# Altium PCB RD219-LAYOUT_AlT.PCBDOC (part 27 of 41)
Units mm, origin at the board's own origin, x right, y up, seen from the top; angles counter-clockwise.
Board outline 209.75 x 159.97 mm, 2 copper layers (TOP, BOTTOM), stack 0 mm thick; 398 components, 199 nets, 1469 pads, 0 vias.
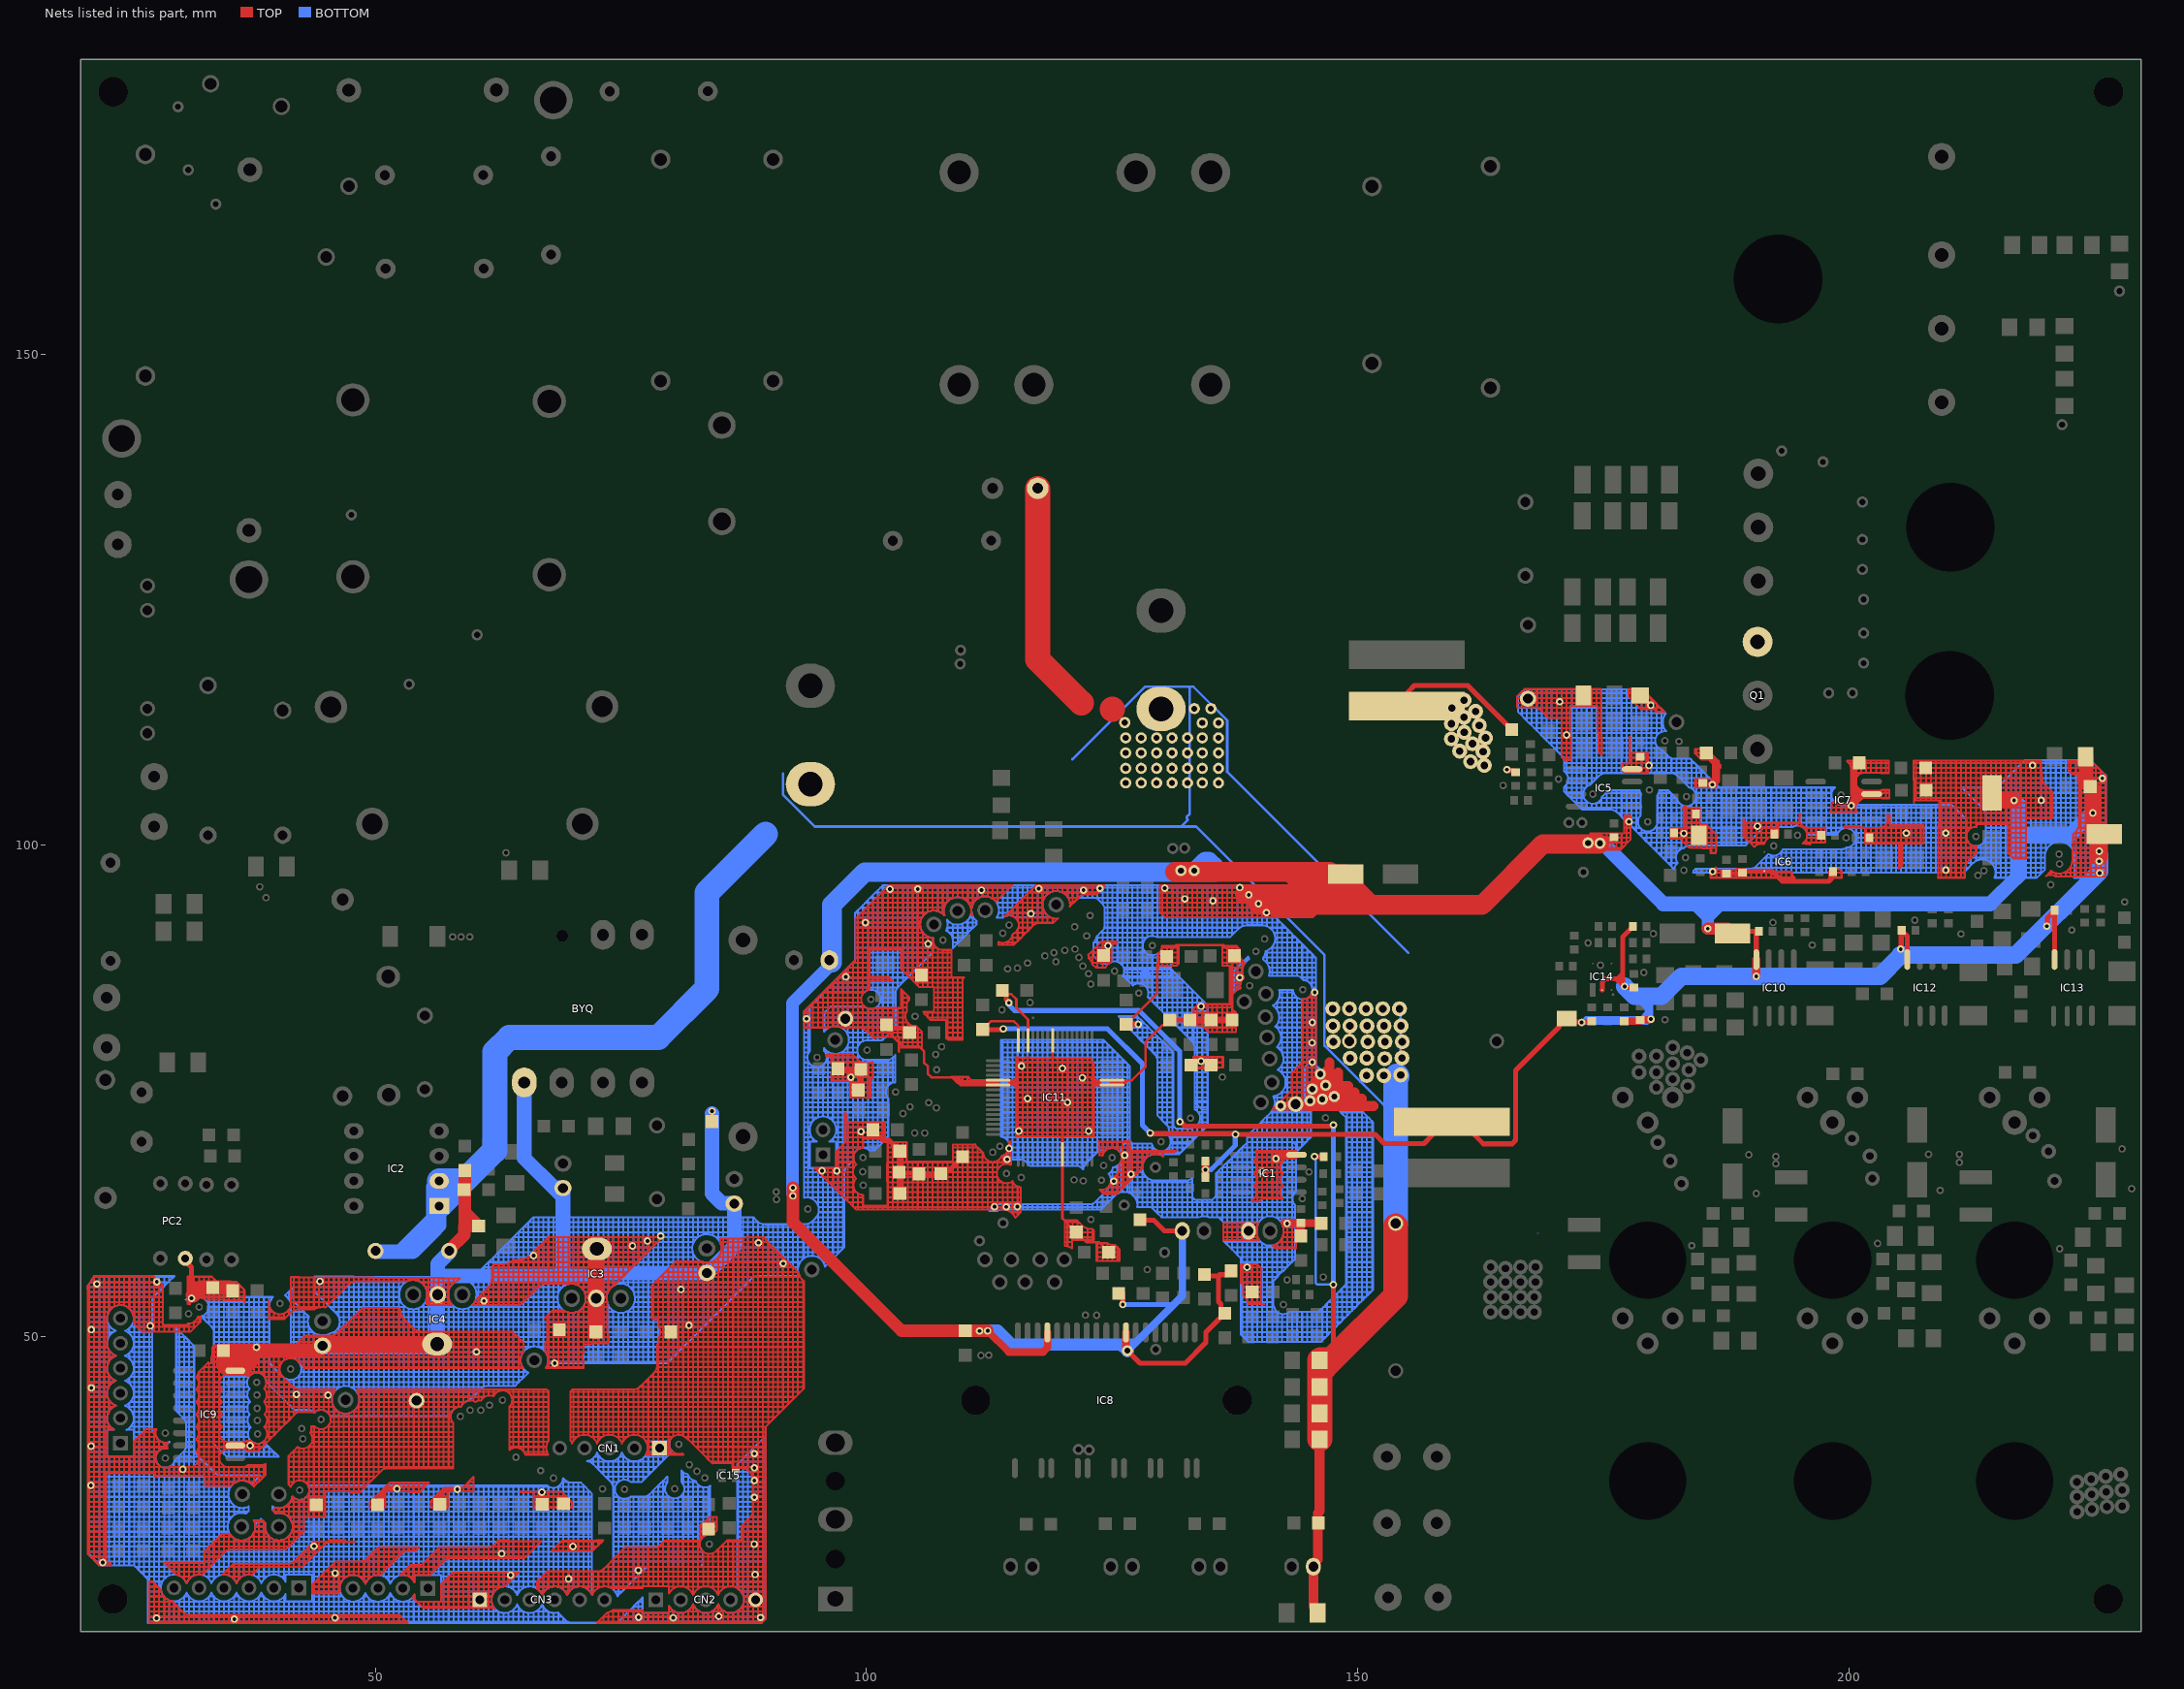
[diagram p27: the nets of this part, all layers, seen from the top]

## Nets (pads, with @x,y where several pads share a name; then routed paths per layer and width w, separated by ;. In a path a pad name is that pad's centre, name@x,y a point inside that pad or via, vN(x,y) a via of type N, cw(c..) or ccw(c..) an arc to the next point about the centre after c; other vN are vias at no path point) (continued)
GND: (continued)
  BOTTOM w0.203: 72.705,61.656 73.213,61.656 ; 72.705,62.164 73.213,62.164 ; 72.83,37.78 ccw(c73.848,38.669) 73.213,37.476 73.213,37.272 ; 72.949,36.256 73.213,36.256 ; 72.949,36.256 73.213,35.992 ; 73.213,35.992 73.213,36.256 ; 73.213,35.992 73.457,35.748 ; 73.213,36.256 73.213,36.764 ; 73.213,36.256 73.721,36.256 ; 73.213,36.764 73.213,37.272 ; 73.213,36.764 73.721,36.764 ; 73.213,37.272 73.721,37.272 ; 73.213,47.319 73.213,47.432 ; 73.213,47.319 73.721,47.319 ; 73.213,47.432 73.213,47.94 ; 73.213,47.432 73.721,47.432 ; 73.213,47.94 73.213,48.448 ; 73.213,47.94 73.721,47.94 ; 73.213,48.448 73.213,48.956 ; 73.213,48.448 73.721,48.448 ; 73.213,48.956 73.213,49.464 ; 73.213,48.956 73.721,48.956 ; 73.213,49.464 73.213,49.972 ; 73.213,49.464 73.721,49.464 ; 73.213,49.972 73.213,50.48 ; 73.213,49.972 73.721,49.972 ; 73.213,50.48 73.213,50.988 ; 73.213,50.48 73.721,50.48 ; 73.213,50.988 73.213,51.496 ; 73.213,50.988 73.721,50.988 ; 73.213,51.496 73.213,52.004 ; 73.213,51.496 73.721,51.496 ; 73.213,52.004 73.213,52.512 ; 73.213,52.004 73.721,52.004 ; 73.213,52.512 73.213,53.02 ; 73.213,52.512 73.721,52.512 ; 73.213,53.02 IC3.2@73.213,53.528 ; 73.213,53.02 73.721,53.02 ; IC3.2@73.213,53.528 73.6,53.528 ; IC3.2@73.213,53.528 IC3.2@73.213,54.036 ; IC3.2@73.213,54.036 73.213,54.544 ; IC3.2@73.213,54.036 73.565,54.036 ; 73.213,54.544 73.213,55.052 ; 73.213,54.544 73.683,54.544 ; 73.213,55.052 73.213,55.56 ; 73.213,55.052 73.721,55.052 ; 73.213,55.56 73.213,56.068 ; 73.213,55.56 73.721,55.56 ; 73.213,56.068 73.213,56.489 73.213,56.576 ; 73.213,56.068 73.721,56.068 ; 73.213,56.576 73.213,57.084 ; 73.213,56.576 73.721,56.576 ; 73.213,57.084 73.213,57.592 ; 73.213,57.084 73.721,57.084 ; 73.213,57.592 IC3.4@73.213,58.1 ; 73.213,57.592 73.721,57.592 ; IC3.4@73.213,58.1 IC3.4@73.213,58.608 ; IC3.4@73.213,58.1 73.721,58.1 ; IC3.4@73.213,58.608 IC3.4@73.721,58.608 ; IC3.4@73.213,58.608 IC3.4@73.213,59.116 ; IC3.4@73.213,59.116 IC3.4@73.213,59.624 ; IC3.4@73.213,59.116 IC3.4@73.721,59.116 ; IC3.4@73.213,59.624 73.213,60.132 ; IC3.4@73.213,59.624 IC3.4@73.721,59.624 ; 73.213,60.132 73.213,60.64 ; 73.213,60.132 73.721,60.132 ; 73.213,60.64 73.213,61.148 ; 73.213,60.64 73.721,60.64 ; 73.213,61.148 73.213,61.656 ; 73.213,61.148 73.721,61.148 ; 73.213,61.656 73.213,62.164 ; 73.213,61.656 73.721,61.656 ; 73.213,62.164 73.721,62.164 ; 73.457,35.748 73.721,35.748 ; 73.457,35.748 73.721,35.484 ; 73.565,54.036 ccw(c74.991,53.973) 73.564,53.973 73.564,53.846 ccw(c74.991,53.846) 73.6,53.528 ; 73.565,54.036 cw(c74.991,53.973) 73.683,54.544 ; 73.6,53.528 ccw(c74.991,53.846) 73.6,53.524 ccw(c74.991,53.846) 73.719,53.198 ccw(c74.991,53.846) 73.721,53.195 ; 73.683,54.544 cw(c74.991,53.973) 73.719,54.62 cw(c74.991,53.973) 73.721,54.623 ; 73.721,35.484 73.721,35.748 ; 73.721,35.748 73.721,36.256 ; 73.721,35.748 74.229,35.748 ; 73.721,36.256 73.721,36.764 ; 73.721,36.256 74.229,36.256 ; 73.721,36.764 73.721,37.272 ; 73.721,36.764 74.229,36.764 ; 73.721,37.272 74.229,37.272 ; 73.721,37.272 73.721,37.323 ; 73.721,37.323 ccw(c73.848,38.669) 73.848,37.317 ccw(c73.848,38.669) 74.229,37.372 ; 73.721,47.319 73.721,47.432 ; 73.721,47.319 74.229,47.319 ; 73.721,47.432 73.721,47.94 ; 73.721,47.432 74.229,47.432 ; 73.721,47.94 73.721,48.448 ; 73.721,47.94 74.229,47.94 ; 73.721,48.448 73.721,48.956 ; 73.721,48.448 74.229,48.448 ; 73.721,48.956 73.721,49.464 ; 73.721,48.956 74.229,48.956 ; 73.721,49.464 73.721,49.972 ; 73.721,49.464 74.229,49.464 ; 73.721,49.972 73.721,50.48 ; 73.721,49.972 74.229,49.972 ; 73.721,50.48 73.721,50.988 ; 73.721,50.48 74.229,50.48 ; 73.721,50.988 73.721,51.496 ; 73.721,50.988 74.229,50.988 ; 73.721,51.496 73.721,52.004 ; 73.721,51.496 74.229,51.496 ; 73.721,52.004 73.721,52.512 ; 73.721,52.004 74.229,52.004 ; 73.721,52.512 73.721,53.02 ; 73.721,52.512 74.229,52.512 ; 73.721,53.02 73.721,53.195 ; 73.721,53.02 73.827,53.02 ; 73.721,53.195 ccw(c74.991,53.846) 73.822,53.027 ccw(c74.991,53.846) 73.827,53.02 ; 73.721,54.623 cw(c74.991,53.973) 74.055,55.05 cw(c74.991,53.973) 74.058,55.052 ; 73.721,54.623 73.721,55.052 ; 73.721,55.052 73.721,55.56 ; 73.721,55.052 74.058,55.052 ; 73.721,55.56 73.721,56.068 ; 73.721,55.56 74.229,55.56 ; 73.721,56.068 73.721,56.489 73.721,56.576 ; 73.721,56.068 74.229,56.068 ; 73.721,56.576 73.721,57.084 ; 73.721,56.576 74.229,56.576 ; 73.721,57.084 73.721,57.592 ; 73.721,57.084 74.229,57.084 ; 73.721,57.592 73.721,58.1 ; 73.721,57.592 74.229,57.592 ; 73.721,58.1 IC3.4@73.721,58.608 ; 73.721,58.1 74.229,58.1 ; IC3.4@73.721,58.608 74.229,58.608 ; IC3.4@73.721,58.608 IC3.4@73.721,59.116 ; IC3.4@73.721,59.116 IC3.4@73.721,59.624 ; IC3.4@73.721,59.116 74.229,59.116 ; IC3.4@73.721,59.624 73.721,60.132 ; IC3.4@73.721,59.624 74.229,59.624 ; 73.721,60.132 73.721,60.64 ; 73.721,60.132 74.229,60.132 ; 73.721,60.64 73.721,61.148 ; 73.721,60.64 74.229,60.64 ; 73.721,61.148 73.721,61.656 ; 73.721,61.148 74.229,61.148 ; 73.721,61.656 73.721,62.164 ; 73.721,61.656 74.229,61.656 ; 73.721,62.164 74.229,62.164 ; 73.962,35.24 ccw(c73.135,34.512) 73.914,35.291 cw(c73.135,34.512) 73.962,35.24 ; 73.962,35.24 cw(c73.135,34.512) 74.215,34.732 ; 73.962,35.24 cw(c73.135,34.512) 74.215,34.732 ; 73.962,35.24 74.229,35.24 ; 74.058,55.052 cw(c74.991,53.973) 74.229,55.179 ; 74.215,34.732 cw(c73.135,34.512) 74.229,34.642 ; 74.215,34.732 cw(c73.135,34.512) 74.229,34.642 ; 74.215,34.732 74.229,34.732 ; 74.229,34.642 cw(c73.135,34.512) 74.237,34.512 ; 74.229,34.642 cw(c73.135,34.512) 74.237,34.512 ; 74.229,34.642 74.229,34.732 ; 74.229,34.732 74.229,35.24 ; 74.229,34.732 74.423,34.732 ; 74.229,35.24 74.737,35.24 ; 74.229,35.24 74.229,35.748 ; 74.229,35.748 74.229,36.256 ; 74.229,35.748 74.737,35.748 ; 74.229,36.256 74.229,36.764 ; 74.229,36.256 74.737,36.256 ; 74.229,36.764 74.229,37.272 ; 74.229,36.764 74.737,36.764 ; 74.229,37.272 74.737,37.272 ; 74.229,37.272 74.229,37.372 ; 74.229,37.372 ccw(c73.848,38.669) 74.737,37.651 ; 74.229,47.319 74.229,47.432 ; 74.229,47.319 74.737,47.319 ; 74.229,47.432 74.229,47.94 ; 74.229,47.432 74.737,47.432 ; 74.229,47.94 74.229,48.448 ; 74.229,47.94 74.737,47.94 ; 74.229,48.448 74.229,48.956 ; 74.229,48.448 74.737,48.448 ; 74.229,48.956 74.229,49.464 ; 74.229,48.956 74.737,48.956 ; 74.229,49.464 74.229,49.972 ; 74.229,49.464 74.737,49.464 ; 74.229,49.972 74.229,50.48 ; 74.229,49.972 74.737,49.972 ; 74.229,50.48 74.229,50.988 ; 74.229,50.48 74.737,50.48 ; 74.229,50.988 74.229,51.496 ; 74.229,50.988 74.737,50.988 ; 74.229,51.496 74.229,52.004 ; 74.229,51.496 74.737,51.496 ; 74.229,52.004 74.229,52.512 ; 74.229,52.004 74.737,52.004 ; 74.229,52.512 74.483,52.512 ; 74.229,55.179 cw(c74.991,53.973) 74.235,55.183 cw(c74.991,53.973) 74.737,55.377 ; 74.229,55.179 74.229,55.56 ; 74.229,55.56 74.229,56.068 ; 74.229,55.56 74.737,55.56 ; 74.229,56.068 74.229,56.489 74.229,56.576 ; 74.229,56.068 74.737,56.068 ; 74.229,56.576 74.229,57.084 ; 74.229,56.576 74.737,56.576 ; 74.229,57.084 74.229,57.592 ; 74.229,57.084 74.737,57.084 ; 74.229,57.592 74.229,58.1 ; 74.229,57.592 74.737,57.592 ; 74.229,58.1 74.229,58.608 ; 74.229,58.1 74.737,58.1 ; 74.229,58.608 74.229,59.116 ; 74.229,58.608 74.737,58.608 ; 74.229,59.116 74.229,59.624 ; 74.229,59.116 74.737,59.116 ; 74.229,59.624 74.229,60.132 ; 74.229,59.624 74.737,59.624 ; 74.229,60.132 74.229,60.64 ; 74.229,60.132 74.737,60.132 ; 74.229,60.64 74.229,61.148 ; 74.229,60.64 74.737,60.64 ; 74.229,61.148 74.229,61.656 ; 74.229,61.148 74.737,61.148 ; 74.229,61.656 74.229,62.164 ; 74.229,61.656 74.737,61.656 ; 74.229,62.164 74.737,62.164 ; 74.237,24.252 cw(c73.34,23.241) 74.405,24.073 cw(c73.34,23.241) 74.412,24.064 ; 74.237,24.252 74.237,24.572 ; 74.237,24.572 74.237,25.08 ; 74.237,24.572 74.737,24.572 ; 74.237,25.08 74.737,25.08 ; 74.237,25.08 74.237,25.588 ; 74.237,25.588 74.237,26.096 ; 74.237,25.588 74.737,25.588 ; 74.237,26.096 74.737,26.096 ; 74.237,26.096 74.237,26.604 ; 74.237,26.604 74.737,26.604 ; 74.237,26.604 74.237,27.112 ; 74.237,27.112 74.737,27.112 ; 74.237,27.112 74.237,27.62 ; 74.237,27.62 74.237,28.128 ; 74.237,27.62 74.737,27.62 ; 74.237,28.128 74.737,28.128 ; 74.237,28.128 74.237,28.636 ; 74.237,28.636 74.737,28.636 ; 74.237,28.636 74.237,29.144 ; 74.237,29.144 74.237,29.652 ; 74.237,29.144 74.737,29.144 ; 74.237,29.652 74.737,29.652 ; 74.237,29.652 74.237,30.16 ; 74.237,30.16 74.737,30.16 ; 74.237,30.16 74.237,30.668 ; 74.237,30.668 74.737,30.668 ; 74.237,30.668 74.237,31.176 ; 74.237,31.176 74.737,31.176 ; 74.237,31.176 74.237,31.684 ; 74.237,31.684 74.737,31.684 ; 74.237,31.684 74.237,32.192 ; 74.237,32.192 74.737,32.192 ; 74.237,32.192 74.237,32.7 ; 74.237,32.7 74.737,32.7 ; 74.237,32.7 74.237,33.208 ; 74.237,33.208 74.237,33.716 ; 74.237,33.208 74.737,33.208 ; 74.237,33.716 74.237,34.224 ; 74.237,33.716 74.737,33.716 ; 74.237,34.224 74.423,34.224 ; 74.237,34.224 74.237,34.512 ; 74.356,20.922 ccw(c74.356,21.651) 74.713,21.016 ; 74.356,20.922 ccw(c74.356,21.651) 74.713,21.016 ; 74.412,24.064 74.737,24.064 ; 74.423,34.224 ccw(c75.372,34.478) 74.737,33.728 ; 74.423,34.224 cw(c75.372,34.478) 74.423,34.732 ; 74.423,34.732 cw(c75.372,34.478) 74.737,35.228 ; 74.483,52.512 ccw(c74.991,53.846) 74.737,52.441 ; 74.713,21.016 ccw(c74.356,21.651) 74.737,21.03 ; 74.713,21.016 ccw(c74.356,21.651) 74.737,21.03 ; 74.713,21.016 74.737,21.016 ; 74.737,20.889 75.245,20.889 ; 74.737,20.889 74.737,21.016 ; 74.737,21.016 75.245,21.016 ; 74.737,21.016 74.737,21.03 ; 74.737,21.03 ccw(c74.356,21.651) 74.871,21.136 ; 74.737,21.03 ccw(c74.356,21.651) 74.871,21.136 ; 74.737,23.697 74.737,24.064 ; 74.737,23.697 75.104,24.064 ; 74.737,24.064 74.737,24.572 ; 74.737,24.064 75.104,24.064 ; 74.737,24.572 74.737,25.08 ; 74.737,24.572 75.245,24.572 ; 74.737,25.08 75.245,25.08 ; 74.737,25.08 74.737,25.588 ; 74.737,25.588 74.737,26.096 ; 74.737,25.588 75.245,25.588 ; 74.737,26.096 75.245,26.096 ; 74.737,26.096 74.737,26.604 ; 74.737,26.604 75.245,26.604 ; 74.737,26.604 74.737,27.112 ; 74.737,27.112 74.737,27.62 ; 74.737,27.112 75.245,27.112 ; 74.737,27.62 74.737,28.128 ; 74.737,27.62 75.245,27.62 ; 74.737,28.128 74.737,28.636 ; 74.737,28.128 75.245,28.128 ; 74.737,28.636 74.737,29.144 ; 74.737,28.636 75.245,28.636 ; 74.737,29.144 74.737,29.652 ; 74.737,29.144 75.245,29.144 ; 74.737,29.652 75.245,29.652 ; 74.737,29.652 74.737,30.16 ; 74.737,30.16 74.737,30.668 ; 74.737,30.16 75.245,30.16 ; 74.737,30.668 74.737,31.176 ; 74.737,30.668 75.245,30.668 ; 74.737,31.176 74.737,31.684 ; 74.737,31.176 75.245,31.176 ; 74.737,31.684 74.737,32.192 ; 74.737,31.684 75.245,31.684 ; 74.737,32.192 74.737,32.7 ; 74.737,32.192 75.245,32.192 ; 74.737,32.7 74.737,33.208 ; 74.737,32.7 75.245,32.7 ; 74.737,33.208 74.737,33.716 ; 74.737,33.208 75.245,33.208 ; 74.737,33.716 74.737,33.728 ; 74.737,33.716 74.752,33.716 ; 74.737,33.728 ccw(c75.372,34.478) 74.752,33.716 ; 74.737,35.228 cw(c75.372,34.478) 74.752,35.24 ; 74.737,35.228 74.737,35.24 ; 74.737,35.24 74.737,35.748 ; 74.737,35.24 74.752,35.24 ; 74.737,35.748 74.737,36.256 ; 74.737,35.748 75.245,35.748 ; 74.737,36.256 74.737,36.764 ; 74.737,36.256 75.245,36.256 ; 74.737,36.764 74.737,37.272 ; 74.737,36.764 75.245,36.764 ; 74.737,37.272 75.245,37.272 ; 74.737,37.272 74.737,37.651 ; 74.737,37.651 ccw(c73.848,38.669) 74.866,37.78 ; 74.737,47.319 74.737,47.432 ; 74.737,47.319 75.245,47.319 ; 74.737,47.432 74.737,47.94 ; 74.737,47.432 75.245,47.432 ; 74.737,47.94 74.737,48.448 ; 74.737,47.94 75.245,47.94 ; 74.737,48.448 74.737,48.956 ; 74.737,48.448 75.245,48.448 ; 74.737,48.956 74.737,49.464 ; 74.737,48.956 75.245,48.956 ; 74.737,49.464 74.737,49.972 ; 74.737,49.464 75.245,49.464 ; 74.737,49.972 74.737,50.48 ; 74.737,49.972 75.245,49.972 ; 74.737,50.48 74.737,50.988 ; 74.737,50.48 75.245,50.48 ; 74.737,50.988 74.737,51.496 ; 74.737,50.988 75.245,50.988 ; 74.737,51.496 74.737,52.004 ; 74.737,51.496 75.245,51.496 ; 74.737,52.004 75.245,52.004 ; 74.737,52.004 74.737,52.441 ; 74.737,52.441 ccw(c74.991,53.846) 74.743,52.44 ccw(c74.991,53.846) 75.245,52.441 ; 74.737,55.377 cw(c74.991,53.973) 74.743,55.378 cw(c74.991,53.973) 74.991,55.4 cw(c74.991,53.973) 75.239,55.378 cw(c74.991,53.973) 75.245,55.377 ; 74.737,55.377 74.737,55.56 ; 74.737,55.56 74.737,56.068 ; 74.737,55.56 75.245,55.56 ; 74.737,56.068 74.737,56.489 74.737,56.576 ; 74.737,56.068 75.245,56.068 ; 74.737,56.576 74.737,57.084 ; 74.737,56.576 75.245,56.576 ; 74.737,57.084 74.737,57.592 ; 74.737,57.084 75.245,57.084 ; 74.737,57.592 74.737,58.1 ; 74.737,57.592 75.245,57.592 ; 74.737,58.1 74.737,58.608 ; 74.737,58.1 75.245,58.1 ; 74.737,58.608 74.737,59.116 ; 74.737,58.608 75.245,58.608 ; 74.737,59.116 74.737,59.624 ; 74.737,59.116 75.245,59.116 ; 74.737,59.624 74.737,60.132 ; 74.737,59.624 75.245,59.624 ; 74.737,60.132 74.737,60.64 ; 74.737,60.132 75.245,60.132 ; 74.737,60.64 74.737,61.148 ; 74.737,60.64 75.245,60.64 ; 74.737,61.148 74.737,61.656 ; 74.737,61.148 75.245,61.148 ; 74.737,61.656 74.737,62.164 ; 74.737,61.656 75.245,61.656 ; 74.737,62.164 75.245,62.164 ; 74.752,33.716 ccw(c75.372,34.478) 75.245,33.504 ; 74.752,35.24 cw(c75.372,34.478) 75.245,35.452 ; 74.866,37.78 ccw(c73.848,38.669) 75.118,38.206 ccw(c76.388,38.669) 75.242,37.953 ccw(c76.388,38.669) 75.245,37.948 ; 74.866,37.78 75.245,37.78 ; 74.871,21.136 75.259,21.524 ; 75.104,24.064 75.245,24.205 ; 75.245,20.889 75.753,20.889 ; 75.245,20.889 75.245,21.016 ; 75.245,21.016 75.753,21.016 ; 75.245,24.205 75.245,24.572 ; 75.245,24.205 75.612,24.572 ; 75.245,24.572 75.245,25.08 ; 75.245,24.572 75.612,24.572 ; 75.245,25.08 75.245,25.588 ; 75.245,25.08 75.753,25.08 ; 75.245,25.588 75.245,26.096 ; 75.245,25.588 75.753,25.588 ; 75.245,26.096 75.245,26.604 ; 75.245,26.096 75.753,26.096 ; 75.245,26.604 75.245,27.112 ; 75.245,26.604 75.753,26.604 ; 75.245,27.112 75.245,27.62 ; 75.245,27.112 75.753,27.112 ; 75.245,27.62 75.245,28.128 ; 75.245,27.62 75.753,27.62 ; 75.245,28.128 75.245,28.636 ; 75.245,28.128 75.753,28.128 ; 75.245,28.636 75.245,29.144 ; 75.245,28.636 75.753,28.636 ; 75.245,29.144 75.245,29.652 ; 75.245,29.144 75.753,29.144 ; 75.245,29.652 75.245,30.16 ; 75.245,29.652 75.753,29.652 ; 75.245,30.16 75.245,30.668 ; 75.245,30.16 75.753,30.16 ; 75.245,30.668 75.245,31.176 ; 75.245,30.668 75.753,30.668 ; 75.245,31.176 75.245,31.684 ; 75.245,31.176 75.753,31.176 ; 75.245,31.684 75.245,32.192 ; 75.245,31.684 75.753,31.684 ; 75.245,32.192 75.245,32.7 ; 75.245,32.192 75.753,32.192 ; 75.245,32.7 75.245,33.208 ; 75.245,32.7 75.753,32.7 ; 75.245,33.208 75.753,33.208 ; 75.245,33.208 75.245,33.504 ; 75.245,33.504 ccw(c75.372,34.478) 75.252,33.503 ccw(c75.372,34.478) 75.753,33.572 ; 75.245,35.452 cw(c75.372,34.478) 75.252,35.453 cw(c75.372,34.478) 75.753,35.384 ; 75.245,35.452 75.245,35.748 ; 75.245,35.748 75.245,36.256 ; 75.245,35.748 75.753,35.748 ; 75.245,36.256 75.245,36.764 ; 75.245,36.256 75.753,36.256 ; 75.245,36.764 75.245,37.272 ; 75.245,36.764 75.753,36.764 ; 75.245,37.272 75.245,37.78 ; 75.245,37.272 75.753,37.272 ; 75.245,37.78 75.37,37.78 ; 75.245,37.78 75.245,37.948 ; 75.245,37.948 ccw(c76.388,38.669) 75.37,37.78 ; 75.245,47.319 75.245,47.432 ; 75.245,47.319 75.753,47.319 ; 75.245,47.432 75.245,47.94 ; 75.245,47.432 75.753,47.432 ; 75.245,47.94 75.245,48.448 ; 75.245,47.94 75.753,47.94 ; 75.245,48.448 75.245,48.956 ; 75.245,48.448 75.753,48.448 ; 75.245,48.956 75.245,49.464 ; 75.245,48.956 75.753,48.956 ; 75.245,49.464 75.245,49.972 ; 75.245,49.464 75.753,49.464 ; 75.245,49.972 75.245,50.48 ; 75.245,49.972 75.753,49.972 ; 75.245,50.48 75.245,50.988 ; 75.245,50.48 75.753,50.48 ; 75.245,50.988 75.245,51.496 ; 75.245,50.988 75.753,50.988 ; 75.245,51.496 75.245,52.004 ; 75.245,51.496 75.753,51.496 ; 75.245,52.004 75.753,52.004 ; 75.245,52.004 75.245,52.441 ; 75.245,52.441 ccw(c74.991,53.846) 75.499,52.512 ; 75.245,55.377 cw(c74.991,53.973) 75.747,55.183 cw(c74.991,53.973) 75.753,55.179 ; 75.245,55.377 75.245,55.56 ; 75.245,55.56 75.245,56.068 ; 75.245,55.56 75.753,55.56 ; 75.245,56.068 75.245,56.489 75.245,56.576 ; 75.245,56.068 75.753,56.068 ; 75.245,56.576 75.245,57.084 ; 75.245,56.576 75.753,56.576 ; 75.245,57.084 75.245,57.592 ; 75.245,57.084 75.753,57.084 ; 75.245,57.592 75.245,58.1 ; 75.245,57.592 75.753,57.592 ; 75.245,58.1 75.245,58.608 ; 75.245,58.1 75.753,58.1 ; 75.245,58.608 75.245,59.116 ; 75.245,58.608 75.753,58.608 ; 75.245,59.116 75.245,59.624 ; 75.245,59.116 75.753,59.116 ; 75.245,59.624 75.245,60.132 ; 75.245,59.624 75.753,59.624 ; 75.245,60.132 75.245,60.64 ; 75.245,60.132 75.753,60.132 ; 75.245,60.64 75.245,61.148 ; 75.245,60.64 75.753,60.64 ; 75.245,61.148 75.245,61.656 ; 75.245,61.148 75.753,61.148 ; 75.245,61.656 75.245,62.164 ; 75.245,61.656 75.753,61.656 ; 75.245,62.164 75.753,62.164 ; 75.259,21.524 75.753,22.018 ; 75.259,21.524 75.753,21.524 ; 75.37,37.78 ccw(c76.388,38.669) 75.753,37.476 75.753,37.272 ; 75.499,52.512 ccw(c74.991,53.846) 75.747,52.635 ccw(c74.991,53.846) 75.753,52.639 ; 75.499,52.512 75.753,52.512 ; 75.612,24.572 75.753,24.713 ; 75.753,20.889 75.753,21.016 ; 75.753,20.889 76.261,20.889 ; 75.753,21.016 75.753,21.524 ; 75.753,21.016 76.261,21.016 ; 75.753,21.524 75.753,22.018 ; 75.753,21.524 76.261,21.524 ; 75.753,22.018 75.767,22.032 ; 75.753,24.713 75.753,25.08 ; 75.753,25.08 75.753,25.588 ; 75.753,25.588 75.753,26.096 ; 75.753,25.588 76.261,25.588 ; 75.753,26.096 76.261,26.096 ; 75.753,26.096 75.753,26.604 ; 75.753,26.604 76.261,26.604 ; 75.753,26.604 75.753,27.112 ; 75.753,27.112 75.753,27.62 ; 75.753,27.112 76.261,27.112 ; 75.753,27.62 75.753,28.128 ; 75.753,27.62 76.261,27.62 ; 75.753,28.128 76.261,28.128 ; 75.753,28.128 75.753,28.636 ; 75.753,28.636 75.753,29.144 ; 75.753,28.636 76.261,28.636 ; 75.753,29.144 75.753,29.652 ; 75.753,29.144 76.261,29.144 ; 75.753,29.652 76.261,29.652 ; 75.753,29.652 75.753,30.16 ; 75.753,30.16 75.753,30.668 ; 75.753,30.16 76.261,30.16 ; 75.753,30.668 75.753,31.176 ; 75.753,30.668 76.261,30.668 ; 75.753,31.176 75.753,31.684 ; 75.753,31.176 76.261,31.176 ; 75.753,31.684 75.753,32.192 ; 75.753,31.684 76.261,31.684 ; 75.753,32.192 75.753,32.7 ; 75.753,32.192 76.261,32.192 ; 75.753,32.7 75.753,33.208 ; 75.753,32.7 76.261,32.7 ; 75.753,33.208 76.261,33.208 ; 75.753,33.208 75.753,33.572 ; 75.753,33.572 ccw(c75.372,34.478) 75.756,33.574 ccw(c75.372,34.478) 75.992,33.716 ; 75.753,35.384 cw(c75.372,34.478) 75.756,35.382 cw(c75.372,34.478) 75.992,35.24 ; 75.753,35.384 75.753,35.748 ; 75.753,35.748 75.753,36.256 ; 75.753,35.748 76.261,35.748 ; 75.753,36.256 75.753,36.764 ; 75.753,36.256 76.261,36.256 ; 75.753,36.764 75.753,37.272 ; 75.753,36.764 76.261,36.764 ; 75.753,37.272 76.261,37.272 ; 75.753,47.319 75.753,47.432 ; 75.753,47.319 76.261,47.319 ; 75.753,47.432 75.753,47.94 ; 75.753,47.432 76.261,47.432 ; 75.753,47.94 75.753,48.448 ; 75.753,47.94 76.261,47.94 ; 75.753,48.448 75.753,48.956 ; 75.753,48.448 76.261,48.448 ; 75.753,48.956 75.753,49.464 ; 75.753,48.956 76.261,48.956 ; 75.753,49.464 75.753,49.972 ; 75.753,49.464 76.261,49.464 ; 75.753,49.972 75.753,50.48 ; 75.753,49.972 76.261,49.972 ; 75.753,50.48 75.753,50.988 ; 75.753,50.48 76.261,50.48 ; 75.753,50.988 75.753,51.496 ; 75.753,50.988 76.261,50.988 ; 75.753,51.496 75.753,52.004 ; 75.753,51.496 76.261,51.496 ; 75.753,52.004 75.753,52.512 ; 75.753,52.004 76.261,52.004 ; 75.753,52.512 76.261,52.512 ; 75.753,52.512 75.753,52.639 ; 75.753,55.179 cw(c74.991,53.973) 75.924,55.052 ; 75.753,55.179 75.753,55.56 ; 75.753,55.56 75.753,56.068 ; 75.753,55.56 76.261,55.56 ; 75.753,56.068 75.753,56.489 75.753,56.576 ; 75.753,56.068 76.261,56.068 ; 75.753,56.576 75.753,57.084 ; 75.753,56.576 76.261,56.576 ; 75.753,57.084 75.753,57.592 ; 75.753,57.084 76.261,57.084 ; 75.753,57.592 75.753,58.1 ; 75.753,57.592 76.261,57.592 ; 75.753,58.1 75.753,58.608 ; 75.753,58.1 76.261,58.1 ; 75.753,58.608 75.753,59.116 ; 75.753,58.608 76.261,58.608 ; 75.753,59.116 pad.@76.261,59.116 ; 75.753,59.116 75.753,59.624 ; 75.753,59.624 75.753,60.132 ; 75.753,59.624 76.261,59.624 ; 75.753,60.132 75.753,60.64 ; 75.753,60.132 76.261,60.132 ; 75.753,60.64 75.753,61.148 ; 75.753,60.64 76.261,60.64 ; 75.753,61.148 75.753,61.656 ; 75.753,61.148 76.261,61.148 ; 75.753,61.656 75.753,62.164 ; 75.753,61.656 76.261,61.656 ; 75.753,62.164 76.261,62.164 ; 75.767,22.032 76.261,22.526 ; 75.767,22.032 76.261,22.032 ; 75.924,55.052 cw(c74.991,53.973) 76.261,54.623 ; 75.924,55.052 76.261,55.052 ; 75.992,33.716 76.261,33.716 ; 75.992,35.24 76.261,35.24 ; 76.261,20.889 76.261,21.016 ; 76.261,20.889 76.769,20.889 ; 76.261,21.016 76.261,21.524 ; 76.261,21.016 76.769,21.016 ; 76.261,21.524 76.261,22.032 ; 76.261,21.524 pad.@76.769,21.524 ; 76.261,22.032 76.261,22.526 ; 76.261,22.032 76.769,22.032 ; 76.261,22.526 76.275,22.54 ; 76.261,25.221 76.628,25.588 ; 76.261,25.221 76.261,25.588 ; 76.261,25.588 76.261,26.096 ; 76.261,25.588 76.628,25.588 ; 76.261,26.096 76.261,26.604 ; 76.261,26.096 pad.@76.769,26.096 ; 76.261,26.604 76.261,27.112 ; 76.261,26.604 76.769,26.604 ; 76.261,27.112 76.261,27.62 ; 76.261,27.112 76.769,27.112 ; 76.261,27.62 76.261,28.128 ; 76.261,27.62 76.769,27.62 ; 76.261,28.128 76.769,28.128 ; 76.261,28.128 76.261,28.636 ; 76.261,28.636 76.261,29.144 ; 76.261,28.636 76.769,28.636 ; 76.261,29.144 76.261,29.652 ; 76.261,29.144 76.769,29.144 ; 76.261,29.652 76.769,29.652 ; 76.261,29.652 76.261,30.16 ; 76.261,30.16 76.261,30.668 ; 76.261,30.16 76.769,30.16 ; 76.261,30.668 76.261,31.176 ; 76.261,30.668 76.769,30.668 ; 76.261,31.176 76.261,31.684 ; 76.261,31.176 76.769,31.176 ; 76.261,31.684 76.261,32.192 ; 76.261,31.684 76.769,31.684 ; 76.261,32.192 76.261,32.7 ; 76.261,32.192 76.769,32.192 ; 76.261,32.7 76.261,33.208 ; 76.261,32.7 76.769,32.7 ; 76.261,33.208 76.261,33.716 ; 76.261,33.208 76.769,33.208 ; 76.261,33.716 76.261,33.749 ; 76.261,33.716 76.769,33.716 ; 76.261,33.749 76.769,33.749 ; 76.261,35.207 76.261,35.24 ; 76.261,35.207 76.769,35.207 ; 76.261,35.24 76.261,35.748 ; 76.261,35.24 76.769,35.24 ; 76.261,35.748 76.261,36.256 ; 76.261,35.748 76.769,35.748 ; 76.261,36.256 76.261,36.764 ; 76.261,36.256 76.769,36.256 ; 76.261,36.764 76.261,37.272 ; 76.261,36.764 76.769,36.764 ; 76.261,37.272 76.769,37.272 ; 76.261,37.272 76.261,37.323 ; 76.261,37.323 ccw(c76.388,38.669) 76.388,37.317 ccw(c76.388,38.669) 76.761,37.37 ccw(c76.388,38.669) 76.769,37.372 ; 76.261,47.319 76.261,47.432 ; 76.261,47.319 76.769,47.319 ; 76.261,47.432 76.261,47.94 ; 76.261,47.432 76.769,47.432 ; 76.261,47.94 76.261,48.448 ; 76.261,47.94 76.769,47.94 ; 76.261,48.448 76.261,48.956 ; 76.261,48.448 76.769,48.448 ; 76.261,48.956 76.261,49.464 ; 76.261,48.956 76.769,48.956 ; 76.261,49.464 76.261,49.972 ; 76.261,49.464 76.769,49.464 ; 76.261,49.972 76.261,50.48 ; 76.261,49.972 76.769,49.972 ; 76.261,50.48 76.261,50.988 ; 76.261,50.48 76.769,50.48 ; 76.261,50.988 76.261,51.496 ; 76.261,50.988 76.769,50.988 ; 76.261,51.496 76.261,52.004 ; 76.261,51.496 76.769,51.496 ; 76.261,52.004 76.261,52.512 ; 76.261,52.004 76.769,52.004 ; 76.261,52.512 76.261,53.02 ; 76.261,52.512 76.769,52.512 ; 76.261,53.02 76.769,53.02 ; 76.261,53.02 76.261,53.195 ; 76.261,53.195 ccw(c74.991,53.846) 76.263,53.198 ccw(c74.991,53.846) 76.382,53.524 ccw(c74.991,53.846) 76.382,53.528 ; 76.261,54.623 cw(c74.991,53.973) 76.295,54.553 cw(c74.991,53.973) 76.299,54.544 ; 76.261,54.623 76.261,55.052 ; 76.261,55.052 76.261,55.56 ; 76.261,55.052 76.769,55.052 ; 76.261,55.56 76.261,56.068 ; 76.261,55.56 76.769,55.56 ; 76.261,56.068 76.261,56.489 76.261,56.576 ; 76.261,56.068 76.769,56.068 ; 76.261,56.576 76.261,57.084 ; 76.261,56.576 76.769,56.576 ; 76.261,57.084 76.261,57.592 ; 76.261,57.084 76.769,57.084 ; 76.261,57.592 76.261,58.1 ; 76.261,57.592 76.769,57.592 ; 76.261,58.1 76.261,58.608 ; 76.261,58.1 76.769,58.1 ; 76.261,58.608 pad.@76.261,59.116 ; 76.261,58.608 76.769,58.608 ; pad.@76.261,59.116 76.769,59.116 ; pad.@76.261,59.116 76.261,59.624 ; 76.261,59.624 76.261,60.132 ; 76.261,59.624 76.769,59.624 ; 76.261,60.132 76.261,60.64 ; 76.261,60.132 76.769,60.132 ; 76.261,60.64 76.261,61.148 ; 76.261,60.64 76.769,60.64 ; 76.261,61.148 76.261,61.656 ; 76.261,61.148 76.769,61.148 ; 76.261,61.656 76.261,62.164 ; 76.261,61.656 76.769,61.656 ; 76.261,62.164 76.769,62.164 ; 76.275,22.54 76.769,22.54 ; 76.275,22.54 76.769,23.034 ; 76.299,54.544 cw(c74.991,53.973) 76.417,54.036 ; 76.299,54.544 76.769,54.544 ; 76.382,53.528 ccw(c74.991,53.846) 76.418,53.846 76.418,53.973 ccw(c74.991,53.973) 76.417,54.036 ; 76.382,53.528 76.769,53.528 ; 76.417,54.036 76.769,54.036 ; 76.628,25.588 76.769,25.729 ; 76.769,20.889 77.277,20.889 ; 76.769,20.889 76.769,21.016 ; 76.769,21.016 pad.@76.769,21.524 ; 76.769,21.016 77.277,21.016 ; pad.@76.769,21.524 76.769,22.032 ; pad.@76.769,21.524 77.277,21.524 ; 76.769,22.032 76.769,22.54 ; 76.769,22.032 77.195,22.032 ; 76.769,22.54 76.769,23.034 ; 76.769,22.54 77.195,22.54 ; 76.769,23.034 76.783,23.048 ; 76.769,25.729 pad.@76.769,26.096 ; 76.769,25.729 77.136,26.096 ; pad.@76.769,26.096 pad.@76.769,26.223 76.769,26.604 ; pad.@76.769,26.096 77.136,26.096 ; 76.769,26.604 76.769,27.112 ; 76.769,26.604 77.277,26.604 ; 76.769,27.112 76.769,27.62 ; 76.769,27.112 77.277,27.112 ; 76.769,27.62 76.769,28.128 ; 76.769,27.62 77.277,27.62 ; 76.769,28.128 77.277,28.128 ; 76.769,28.128 76.769,28.636 ; 76.769,28.636 76.769,29.144 ; 76.769,28.636 77.277,28.636 ; 76.769,29.144 76.769,29.652 ; 76.769,29.144 77.277,29.144 ; 76.769,29.652 77.277,29.652 ; 76.769,29.652 76.769,30.16 ; 76.769,30.16 76.769,30.668 ; 76.769,30.16 77.277,30.16 ; 76.769,30.668 76.769,31.176 ; 76.769,30.668 77.277,30.668 ; 76.769,31.176 76.769,31.684 ; 76.769,31.176 77.277,31.176 ; 76.769,31.684 76.769,32.192 ; 76.769,31.684 77.277,31.684 ; 76.769,32.192 76.769,32.7 ; 76.769,32.192 77.277,32.192 ; 76.769,32.7 76.769,33.208 ; 76.769,32.7 77.277,32.7 ; 76.769,33.208 76.769,33.716 ; 76.769,33.208 77.277,33.208 ; 76.769,33.716 77.277,33.716 ; 76.769,33.716 76.769,33.749 ; 76.769,33.749 77.277,33.749 ; 76.769,35.207 76.769,35.24 ; 76.769,35.207 77.102,35.207 77.277,35.381 ; 76.769,35.24 76.769,35.748 ; 76.769,35.748 76.769,36.256 ; 76.769,35.748 77.277,35.748 ; 76.769,36.256 76.769,36.764 ; 76.769,36.256 77.277,36.256 ; 76.769,36.764 76.769,37.272 ; 76.769,36.764 77.277,36.764 ; 76.769,37.272 77.277,37.272 ; 76.769,37.272 76.769,37.372 ; 76.769,37.372 ccw(c76.388,38.669) 77.277,37.651 ; 76.769,47.319 76.769,47.432 ; 76.769,47.319 77.277,47.319 ; 76.769,47.432 76.769,47.94 ; 76.769,47.432 77.277,47.432 ; 76.769,47.94 76.769,48.448 ; 76.769,47.94 77.277,47.94 ; 76.769,48.448 76.769,48.956 ; 76.769,48.448 77.277,48.448 ; 76.769,48.956 76.769,49.464 ; 76.769,48.956 77.277,48.956 ; 76.769,49.464 76.769,49.972 ; 76.769,49.464 77.277,49.464 ; 76.769,49.972 76.769,50.48 ; 76.769,49.972 77.277,49.972 ; 76.769,50.48 76.769,50.988 ; 76.769,50.48 77.277,50.48 ; 76.769,50.988 76.769,51.496 ; 76.769,50.988 77.277,50.988 ; 76.769,51.496 76.769,52.004 ; 76.769,51.496 77.277,51.496 ; 76.769,52.004 76.769,52.512 ; 76.769,52.004 77.277,52.004 ; 76.769,52.512 76.769,53.02 ; 76.769,52.512 77.277,52.512 ; 76.769,53.02 76.769,53.528 ; 76.769,53.02 77.277,53.02 ; 76.769,53.528 76.769,54.036 ; 76.769,53.528 77.277,53.528 ; 76.769,54.036 76.769,54.544 ; 76.769,54.036 77.277,54.036 ; 76.769,54.544 76.769,55.052 ; 76.769,54.544 77.277,54.544 ; 76.769,55.052 76.769,55.56 ; 76.769,55.052 77.277,55.052 ; 76.769,55.56 76.769,56.068 ; 76.769,55.56 77.277,55.56 ; 76.769,56.068 76.769,56.489 76.769,56.576 ; 76.769,56.068 77.277,56.068 ; 76.769,56.576 76.769,57.084 ; 76.769,56.576 77.277,56.576 ; 76.769,57.084 76.769,57.592 ; 76.769,57.084 77.277,57.084 ; 76.769,57.592 76.769,58.1 ; 76.769,57.592 77.277,57.592 ; 76.769,58.1 76.769,58.608 ; 76.769,58.1 77.277,58.1 ; 76.769,58.608 76.769,59.116 ; 76.769,58.608 77.277,58.608 ; 76.769,59.116 76.769,59.624 ; 76.769,59.116 77.277,59.116 ; 76.769,59.624 76.769,60.132 ; 76.769,59.624 77.277,59.624 ; 76.769,60.132 76.769,60.64 ; 76.769,60.132 77.277,60.132 ; 76.769,60.64 76.769,61.148 ; 76.769,60.64 77.277,60.64 ; 76.769,61.148 76.769,61.656 ; 76.769,61.148 77.277,61.148 ; 76.769,61.656 76.769,62.164 ; 76.769,61.656 77.277,61.656 ; 76.769,62.164 77.277,62.164 ; 76.783,23.048 77.195,23.46 77.195,23.048 ; 76.783,23.048 77.195,23.048 ; 77.136,26.096 77.277,26.237 ; 77.195,22.032 77.195,22.54 ; 77.195,22.032 77.195,21.889 77.277,21.889 ; 77.195,22.54 77.195,23.048 ; 77.277,20.889 77.277,21.016 ; 77.277,20.889 77.785,20.889 ; 77.277,21.016 77.785,21.016 ; 77.277,21.016 77.277,21.524 ; 77.277,21.524 77.277,21.889 ; 77.277,21.524 77.785,21.524 ; 77.277,21.889 77.785,21.889 ; 77.277,26.237 77.277,26.604 ; 77.277,26.237 77.397,26.357 ; 77.277,26.604 77.785,26.604 ; 77.277,26.604 77.277,27.112 ; 77.277,27.112 77.277,27.62 ; 77.277,27.112 77.785,27.112 ; 77.277,27.62 77.277,28.128 ; 77.277,27.62 77.785,27.62 ; 77.277,28.128 77.785,28.128 ; 77.277,28.128 77.277,28.636 ; 77.277,28.636 77.277,29.144 ; 77.277,28.636 77.785,28.636 ; 77.277,29.144 77.277,29.652 ; 77.277,29.144 77.785,29.144 ; 77.277,29.652 77.785,29.652 ; 77.277,29.652 77.277,30.16 ; 77.277,30.16 77.277,30.668 ; 77.277,30.16 77.785,30.16 ; 77.277,30.668 77.277,31.176 ; 77.277,30.668 77.785,30.668 ; 77.277,31.176 77.277,31.684 ; 77.277,31.176 77.785,31.176 ; 77.277,31.684 77.277,32.192 ; 77.277,31.684 77.785,31.684 ; 77.277,32.192 77.277,32.7 ; 77.277,32.192 77.785,32.192 ; 77.277,32.7 77.277,33.208 ; 77.277,32.7 77.785,32.7 ; 77.277,33.208 77.277,33.716 ; 77.277,33.208 77.785,33.208 ; 77.277,33.716 77.785,33.716 ; 77.277,33.716 77.277,33.749 ; 77.277,33.749 77.404,33.749 ; 77.277,35.381 77.644,35.748 ; 77.277,35.381 77.277,35.748 ; 77.277,35.748 77.277,36.256 ; 77.277,35.748 77.644,35.748 ; 77.277,36.256 77.277,36.764 ; 77.277,36.256 77.785,36.256 ; 77.277,36.764 77.277,37.272 ; 77.277,36.764 77.785,36.764 ; 77.277,37.272 77.785,37.272 ; 77.277,37.272 77.277,37.651 ; 77.277,37.651 ccw(c76.388,38.669) 77.406,37.78 ; 77.277,47.319 77.277,47.432 ; 77.277,47.319 77.785,47.319 ; 77.277,47.432 77.277,47.94 ; 77.277,47.432 77.785,47.432 ; 77.277,47.94 77.277,48.448 ; 77.277,47.94 77.785,47.94 ; 77.277,48.448 77.277,48.956 ; 77.277,48.448 77.785,48.448 ; 77.277,48.956 77.277,49.464 ; 77.277,48.956 77.785,48.956 ; 77.277,49.464 77.277,49.972 ; 77.277,49.464 77.785,49.464 ; 77.277,49.972 77.277,50.48 ; 77.277,49.972 77.785,49.972 ; 77.277,50.48 77.277,50.988 ; 77.277,50.48 77.785,50.48 ; 77.277,50.988 77.277,51.496 ; 77.277,50.988 77.785,50.988 ; 77.277,51.496 77.277,52.004 ; 77.277,51.496 77.785,51.496 ; 77.277,52.004 77.277,52.512 ; 77.277,52.004 77.785,52.004 ; 77.277,52.512 77.277,53.02 ; 77.277,52.512 77.785,52.512 ; 77.277,53.02 77.277,53.528 ; 77.277,53.02 77.785,53.02 ; 77.277,53.528 77.277,54.036 ; 77.277,53.528 77.785,53.528 ; 77.277,54.036 77.277,54.544 ; 77.277,54.036 77.785,54.036 ; 77.277,54.544 77.277,55.052 ; 77.277,54.544 77.785,54.544 ; 77.277,55.052 77.277,55.56 ; 77.277,55.052 77.785,55.052 ; 77.277,55.56 77.277,56.068 ; 77.277,55.56 77.785,55.56 ; 77.277,56.068 77.277,56.489 77.277,56.576 ; 77.277,56.068 77.785,56.068 ; 77.277,56.576 77.277,57.084 ; 77.277,56.576 77.785,56.576 ; 77.277,57.084 77.277,57.592 ; 77.277,57.084 77.785,57.084 ; 77.277,57.592 77.277,58.1 ; 77.277,57.592 77.785,57.592 ; 77.277,58.1 77.277,58.608 ; 77.277,58.1 77.785,58.1 ; 77.277,58.608 77.277,59.116 ; 77.277,58.608 77.785,58.608 ; 77.277,59.116 77.277,59.624 ; 77.277,59.116 77.785,59.116 ; 77.277,59.624 pad.@77.785,59.624 ; 77.277,59.624 77.277,60.132 ; 77.277,60.132 77.277,60.64 ; 77.277,60.132 77.785,60.132 ; 77.277,60.64 77.277,61.148 ; 77.277,60.64 77.785,60.64 ; 77.277,61.148 77.277,61.656 ; 77.277,61.148 77.785,61.148 ; 77.277,61.656 77.277,62.164 ; 77.277,61.656 77.785,61.656 ; 77.277,62.164 77.785,62.164 ; 77.397,26.357 cw(c77.912,25.842) 77.785,26.559 ; 77.397,26.357 cw(c77.912,25.842) 77.785,26.559 ; 77.404,33.749 ccw(c77.404,34.478) 77.785,33.857 ; 77.404,33.749 ccw(c77.404,34.478) 77.785,33.857 ; 77.406,37.78 77.785,37.78 ; 77.563,39.337 cw(c76.388,38.669) 77.581,39.304 ; 77.563,39.337 77.785,39.337 ; 77.581,39.304 cw(c76.388,38.669) 77.734,38.796 ; 77.581,39.304 77.785,39.304 ; 77.644,35.748 77.785,35.889 ; 77.685,38.288 ccw(c76.388,38.669) 77.74,38.669 ccw(c76.388,38.669) 77.734,38.796 ; 77.685,38.288 77.785,38.288 ; 77.734,38.796 77.785,38.796 ; 77.785,20.889 77.785,21.016 ; 77.785,20.889 78.293,20.889 ; 77.785,21.016 77.785,21.524 ; 77.785,21.016 78.293,21.016 ; 77.785,21.524 77.785,21.889 ; 77.785,21.524 78.293,21.524 ; 77.785,21.889 78.293,21.889 ; 77.785,26.559 cw(c77.912,25.842) 77.912,26.571 ; 77.785,26.559 cw(c77.912,25.842) 77.912,26.571 ; 77.785,26.559 77.785,26.604 ; 77.785,26.604 78.293,26.604 ; 77.785,26.604 77.785,27.112 ; 77.785,27.112 77.785,27.62 ; 77.785,27.112 78.293,27.112 ; 77.785,27.62 77.785,28.128 ; 77.785,27.62 78.293,27.62 ; 77.785,28.128 77.785,28.636 ; 77.785,28.128 78.293,28.128 ; 77.785,28.636 77.785,29.144 ; 77.785,28.636 78.293,28.636 ; 77.785,29.144 77.785,29.652 ; 77.785,29.144 78.293,29.144 ; 77.785,29.652 78.293,29.652 ; 77.785,29.652 77.785,30.16 ; 77.785,30.16 77.785,30.668 ; 77.785,30.16 78.293,30.16 ; 77.785,30.668 77.785,31.176 ; 77.785,30.668 78.293,30.668 ; 77.785,31.176 77.785,31.684 ; 77.785,31.176 78.293,31.176 ; 77.785,31.684 77.785,32.192 ; 77.785,31.684 78.293,31.684 ; 77.785,32.192 77.785,32.7 ; 77.785,32.192 78.293,32.192 ; 77.785,32.7 77.785,33.208 ; 77.785,32.7 78.293,32.7 ; 77.785,33.208 77.785,33.716 ; 77.785,33.208 78.293,33.208 ; 77.785,33.716 78.293,33.716 ; 77.785,33.716 77.785,33.857 ; 77.785,33.857 ccw(c77.404,34.478) 77.919,33.963 ; 77.785,33.857 ccw(c77.404,34.478) 77.919,33.963 ; 77.785,35.889 77.785,36.256 ; 77.785,35.889 78.152,36.256 ; 77.785,36.256 77.785,36.764 ; 77.785,36.256 78.152,36.256 ; 77.785,36.764 78.293,36.764 ; 77.785,36.764 77.785,37.272 ; 77.785,37.272 78.293,37.272 ; 77.785,37.272 77.785,37.78 ; 77.785,37.78 77.785,38.288 ; 77.785,37.78 78.293,37.78 ; 77.785,38.288 77.785,38.796 ; 77.785,38.288 CN1.1@78.293,38.288 ; 77.785,38.796 CN1.1@78.293,38.796 ; 77.785,38.796 77.785,39.304 ; 77.785,39.304 77.785,39.337 ; 77.785,39.304 CN1.1@78.293,39.304 ; 77.785,39.337 CN1.1@78.293,39.337 ; 77.785,47.319 77.785,47.432 ; 77.785,47.319 78.293,47.319 ; 77.785,47.432 77.785,47.94 ; 77.785,47.432 78.293,47.432 ; 77.785,47.94 77.785,48.448 ; 77.785,47.94 78.293,47.94 ; 77.785,48.448 77.785,48.956 ; 77.785,48.448 78.293,48.448 ; 77.785,48.956 77.785,49.464 ; 77.785,48.956 78.293,48.956 ; 77.785,49.464 77.785,49.972 ; 77.785,49.464 78.293,49.464 ; 77.785,49.972 77.785,50.48 ; 77.785,49.972 78.293,49.972 ; 77.785,50.48 77.785,50.988 ; 77.785,50.48 78.293,50.48 ; 77.785,50.988 77.785,51.496 ; 77.785,50.988 78.293,50.988 ; 77.785,51.496 77.785,52.004 ; 77.785,51.496 78.293,51.496 ; 77.785,52.004 77.785,52.512 ; 77.785,52.004 78.293,52.004 ; 77.785,52.512 77.785,53.02 ; 77.785,52.512 78.293,52.512 ; 77.785,53.02 77.785,53.528 ; 77.785,53.02 78.293,53.02 ; 77.785,53.528 77.785,54.036 ; 77.785,53.528 78.293,53.528 ; 77.785,54.036 77.785,54.544 ; 77.785,54.036 78.293,54.036 ; 77.785,54.544 77.785,55.052 ; 77.785,54.544 78.293,54.544 ; 77.785,55.052 77.785,55.56 ; 77.785,55.052 78.293,55.052 ; 77.785,55.56 77.785,56.068 ; 77.785,55.56 78.293,55.56 ; 77.785,56.068 77.785,56.489 77.785,56.576 ; 77.785,56.068 78.293,56.068 ; 77.785,56.576 77.785,57.084 ; 77.785,56.576 78.293,56.576 ; 77.785,57.084 77.785,57.592 ; 77.785,57.084 78.293,57.084 ; 77.785,57.592 77.785,58.1 ; 77.785,57.592 78.293,57.592 ; 77.785,58.1 77.785,58.608 ; 77.785,58.1 78.293,58.1 ; 77.785,58.608 77.785,59.116 ; 77.785,58.608 78.293,58.608 ; 77.785,59.116 pad.@77.785,59.624 ; 77.785,59.116 78.293,59.116 ; pad.@77.785,59.624 78.293,59.624 ; pad.@77.785,59.624 77.785,60.132 ; 77.785,60.132 77.785,60.64 ; 77.785,60.132 78.293,60.132 ; 77.785,60.64 77.785,61.148 ; 77.785,60.64 78.293,60.64 ; 77.785,61.148 77.785,61.656 ; 77.785,61.148 78.293,61.148 ; 77.785,61.656 77.785,62.164 ; 77.785,61.656 78.293,61.656 ; 77.785,62.164 78.293,62.164 ; 77.912,26.571 78.293,26.571 ; 77.919,33.963 78.18,34.224 ; 78.152,36.256 78.293,36.397 ; 78.18,34.224 78.293,34.337 ; 78.18,34.224 78.293,34.224 ; 78.293,20.889 78.293,21.016 ; 78.293,20.889 78.801,20.889 ; 78.293,21.016 78.293,21.524 ; 78.293,21.016 78.801,21.016 ; 78.293,21.524 78.293,21.889 ; 78.293,21.524 78.801,21.524 ; 78.293,21.889 78.801,21.889 ; 78.293,26.571 78.293,26.604 ; 78.293,26.571 78.801,26.571 ; 78.293,26.604 78.293,27.112 ; 78.293,26.604 78.801,26.604 ; 78.293,27.112 78.293,27.62 ; 78.293,27.112 78.801,27.112 ; 78.293,27.62 78.293,28.128 ; 78.293,27.62 78.801,27.62 ; 78.293,28.128 78.293,28.636 ; 78.293,28.128 78.801,28.128 ; 78.293,28.636 78.293,29.144 ; 78.293,28.636 78.801,28.636 ; 78.293,29.144 78.293,29.652 ; 78.293,29.144 78.801,29.144 ; 78.293,29.652 78.293,30.16 ; 78.293,29.652 78.801,29.652 ; 78.293,30.16 78.293,30.668 ; 78.293,30.16 78.801,30.16 ; 78.293,30.668 78.293,31.176 ; 78.293,30.668 78.801,30.668 ; 78.293,31.176 78.293,31.684 ; 78.293,31.176 78.801,31.176 ; 78.293,31.684 78.293,32.192 ; 78.293,31.684 78.801,31.684 ; 78.293,32.192 78.293,32.7 ; 78.293,32.192 78.801,32.192 ; 78.293,32.7 78.293,33.208 ; 78.293,32.7 78.801,32.7 ; 78.293,33.208 78.293,33.716 ; 78.293,33.208 78.801,33.208 ; 78.293,33.716 78.293,34.224 ; 78.293,33.716 78.801,33.716 ; 78.293,34.224 78.801,34.224 ; 78.293,34.224 78.293,34.337 ; 78.293,34.337 78.688,34.732 ; 78.293,36.397 78.293,36.764 ; 78.293,36.397 78.66,36.764 ; 78.293,36.764 78.293,37.272 ; 78.293,36.764 78.66,36.764 ; 78.293,37.272 78.293,37.78 ; 78.293,37.272 78.801,37.272 ; 78.293,37.78 CN1.1@78.293,38.288 ; 78.293,37.78 78.801,37.78 ; CN1.1@78.293,38.288 CN1.1@78.801,38.288 ; CN1.1@78.293,38.288 CN1.1@78.293,38.796 ; CN1.1@78.293,38.796 CN1.1@78.293,39.304 ; CN1.1@78.293,38.796 CN1.1@78.801,38.796 ; CN1.1@78.293,39.304 CN1.1@78.293,39.337 ; CN1.1@78.293,39.304 CN1.1@78.801,39.304 ; CN1.1@78.293,39.337 CN1.1@78.801,39.337 ; 78.293,47.319 78.293,47.432 ; 78.293,47.319 78.801,47.319 ; 78.293,47.432 78.293,47.94 ; 78.293,47.432 78.801,47.432 ; 78.293,47.94 78.293,48.448 ; 78.293,47.94 78.801,47.94 ; 78.293,48.448 78.293,48.956 ; 78.293,48.448 78.801,48.448 ; 78.293,48.956 78.293,49.464 ; 78.293,48.956 78.801,48.956 ; 78.293,49.464 78.293,49.972 ; 78.293,49.464 78.801,49.464 ; 78.293,49.972 78.293,50.48 ; 78.293,49.972 78.801,49.972 ; 78.293,50.48 78.293,50.988 ; 78.293,50.48 78.801,50.48 ; 78.293,50.988 78.293,51.496 ; 78.293,50.988 78.801,50.988 ; 78.293,51.496 78.293,52.004 ; 78.293,51.496 78.801,51.496 ; 78.293,52.004 78.293,52.512 ; 78.293,52.004 78.801,52.004 ; 78.293,52.512 78.293,53.02 ; 78.293,52.512 78.801,52.512 ; 78.293,53.02 78.293,53.528 ; 78.293,53.02 78.801,53.02 ; 78.293,53.528 78.293,54.036 ; 78.293,53.528 78.801,53.528 ; 78.293,54.036 78.293,54.544 ; 78.293,54.036 78.801,54.036 ; 78.293,54.544 78.293,55.052 ; 78.293,54.544 78.801,54.544 ; 78.293,55.052 78.293,55.56 ; 78.293,55.052 78.801,55.052 ; 78.293,55.56 78.293,56.068 ; 78.293,55.56 78.801,55.56 ; 78.293,56.068 78.293,56.489 78.293,56.576 ; 78.293,56.068 78.801,56.068 ; 78.293,56.576 78.293,57.084 ; 78.293,56.576 78.801,56.576 ; 78.293,57.084 78.293,57.592 ; 78.293,57.084 78.801,57.084 ; 78.293,57.592 78.293,58.1 ; 78.293,57.592 78.801,57.592 ; 78.293,58.1 78.293,58.608 ; 78.293,58.1 78.801,58.1 ; 78.293,58.608 78.293,59.116 ; 78.293,58.608 78.801,58.608 ; 78.293,59.116 78.293,59.624 ; 78.293,59.116 78.801,59.116 ; 78.293,59.624 78.293,60.132 ; 78.293,59.624 78.801,59.624 ; 78.293,60.132 78.293,60.64 ; 78.293,60.132 pad.@78.801,60.132 ; 78.293,60.64 78.293,61.148 ; 78.293,60.64 78.801,60.64 ; 78.293,61.148 78.293,61.656 ; 78.293,61.148 78.801,61.148 ; 78.293,61.656 78.293,62.164 ; 78.293,61.656 78.801,61.656 ; 78.293,62.164 78.801,62.164 ; 78.66,36.764 78.801,36.905 ; 78.688,34.732 78.801,34.732 ; 78.688,34.732 78.801,34.845 ; 78.801,20.889 78.801,21.016 ; 78.801,20.889 79.309,20.889 ; 78.801,21.016 78.801,21.524 ; 78.801,21.016 79.309,21.016 ; 78.801,21.524 78.801,21.889 ; 78.801,21.524 79.309,21.524 ; 78.801,21.889 79.309,21.889 ; 78.801,26.571 79.309,26.571 ; 78.801,26.571 78.801,26.604 ; 78.801,26.604 79.309,26.604 ; 78.801,26.604 78.801,27.112 ; 78.801,27.112 78.801,27.62 ; 78.801,27.112 79.309,27.112 ; 78.801,27.62 78.801,28.128 ; 78.801,27.62 79.309,27.62 ; 78.801,28.128 79.309,28.128 ; 78.801,28.128 78.801,28.636 ; 78.801,28.636 78.801,29.144 ; 78.801,28.636 79.309,28.636 ; 78.801,29.144 78.801,29.652 ; 78.801,29.144 79.309,29.144 ; 78.801,29.652 79.309,29.652 ; 78.801,29.652 78.801,30.16 ; 78.801,30.16 78.801,30.668 ; 78.801,30.16 79.309,30.16 ; 78.801,30.668 78.801,31.176 ; 78.801,30.668 79.309,30.668 ; 78.801,31.176 78.801,31.684 ; 78.801,31.176 79.309,31.176 ; 78.801,31.684 78.801,32.192 ; 78.801,31.684 79.309,31.684 ; 78.801,32.192 78.801,32.7 ; 78.801,32.192 79.309,32.192 ; 78.801,32.7 78.801,33.208 ; 78.801,32.7 79.309,32.7 ; 78.801,33.208 78.801,33.716 ; 78.801,33.208 79.309,33.208 ; 78.801,33.716 79.309,33.716 ; 78.801,33.716 78.801,34.224 ; 78.801,34.224 78.801,34.732 ; 78.801,34.224 79.309,34.224 ; 78.801,34.732 79.309,34.732 ; 78.801,34.732 78.801,34.845 ; 78.801,34.845 79.196,35.24 ; 78.801,36.905 78.801,37.272 ; 78.801,36.905 79.168,37.272 ; 78.801,37.272 78.801,37.78 ; 78.801,37.272 79.168,37.272 ; 78.801,37.78 CN1.1@78.801,38.288 ; 78.801,37.78 79.309,37.78 ; CN1.1@78.801,38.288 CN1.1@79.309,38.288 ; CN1.1@78.801,38.288 CN1.1@78.801,38.796 ; CN1.1@78.801,38.796 CN1.1@78.801,39.304 ; CN1.1@78.801,38.796 CN1.1@79.309,38.796 ; CN1.1@78.801,39.304 CN1.1@78.801,39.337 ; CN1.1@78.801,39.304 CN1.1@79.309,39.304 ; CN1.1@78.801,39.337 CN1.1@79.309,39.337 ; 78.801,47.319 78.801,47.432 ; 78.801,47.319 79.309,47.319 ; 78.801,47.432 78.801,47.94 ; 78.801,47.432 79.309,47.432 ; 78.801,47.94 78.801,48.448 ; 78.801,47.94 79.309,47.94 ; 78.801,48.448 78.801,48.956 ; 78.801,48.448 79.309,48.448 ; 78.801,48.956 78.801,49.464 ; 78.801,48.956 79.309,48.956 ; 78.801,49.464 78.801,49.972 ; 78.801,49.464 79.309,49.464 ; 78.801,49.972 78.801,50.48 ; 78.801,49.972 79.309,49.972 ; 78.801,50.48 78.801,50.988 ; 78.801,50.48 79.309,50.48 ; 78.801,50.988 78.801,51.496 ; 78.801,50.988 79.309,50.988 ; 78.801,51.496 78.801,52.004 ; 78.801,51.496 79.309,51.496 ; 78.801,52.004 78.801,52.512 ; 78.801,52.004 79.309,52.004 ; 78.801,52.512 78.801,53.02 ; 78.801,52.512 79.309,52.512 ; 78.801,53.02 78.801,53.528 ; 78.801,53.02 79.309,53.02 ; 78.801,53.528 78.801,54.036 ; 78.801,53.528 79.309,53.528 ; 78.801,54.036 78.801,54.544 ; 78.801,54.036 79.309,54.036 ; 78.801,54.544 78.801,55.052 ; 78.801,54.544 79.309,54.544 ; 78.801,55.052 78.801,55.56 ; 78.801,55.052 79.309,55.052 ; 78.801,55.56 78.801,56.068 ; 78.801,55.56 79.309,55.56 ; 78.801,56.068 78.801,56.489 78.801,56.576 ; 78.801,56.068 79.309,56.068 ; 78.801,56.576 78.801,57.084 ; 78.801,56.576 79.309,56.576 ; 78.801,57.084 78.801,57.592 ; 78.801,57.084 79.309,57.084 ; 78.801,57.592 78.801,58.1 ; 78.801,57.592 79.309,57.592 ; 78.801,58.1 78.801,58.608 ; 78.801,58.1 79.309,58.1 ; 78.801,58.608 78.801,59.116 ; 78.801,58.608 79.309,58.608 ; 78.801,59.116 78.801,59.624 ; 78.801,59.116 79.309,59.116 ; 78.801,59.624 pad.@78.801,60.132 ; 78.801,59.624 79.309,59.624 ; pad.@78.801,60.132 78.801,60.64 ; pad.@78.801,60.132 pad.@79.309,60.132 ; 78.801,60.64 78.801,61.148 ; 78.801,60.64 79.309,60.64 ; 78.801,61.148 78.801,61.656 ; 78.801,61.148 79.309,61.148 ; 78.801,61.656 78.801,62.164 ; 78.801,61.656 79.309,61.656 ; 78.801,62.164 79.309,62.164 ; 79.168,37.272 79.309,37.413 ; 79.196,35.24 79.309,35.353 ; 79.196,35.24 79.309,35.24 ; 79.309,20.889 79.817,20.889 ; 79.309,20.889 79.309,21.016 ; 79.309,21.016 79.817,21.016 ; 79.309,21.016 79.309,21.524 ; 79.309,21.524 79.817,21.524 ; 79.309,21.524 79.309,21.889 ; 79.309,21.889 79.817,21.889 ; 79.309,26.571 79.309,26.604 ; 79.309,26.571 79.817,26.571 ; 79.309,26.604 79.309,27.112 ; 79.309,26.604 79.817,26.604 ; 79.309,27.112 79.309,27.62 ; 79.309,27.112 79.817,27.112 ; 79.309,27.62 79.309,28.128 ; 79.309,27.62 79.817,27.62 ; 79.309,28.128 79.309,28.636 ; 79.309,28.128 79.817,28.128 ; 79.309,28.636 79.309,29.144 ; 79.309,28.636 79.817,28.636 ; 79.309,29.144 79.309,29.652 ; 79.309,29.144 79.817,29.144 ; 79.309,29.652 79.817,29.652 ; 79.309,29.652 79.309,30.16 ; 79.309,30.16 79.309,30.668 ; 79.309,30.16 79.817,30.16 ; 79.309,30.668 79.309,31.176 ; 79.309,30.668 79.817,30.668 ; 79.309,31.176 79.309,31.684 ; 79.309,31.176 79.817,31.176 ; 79.309,31.684 79.309,32.192 ; 79.309,31.684 79.817,31.684 ; 79.309,32.192 79.309,32.7 ; 79.309,32.192 79.817,32.192 ; 79.309,32.7 79.309,33.208 ; 79.309,32.7 79.817,32.7 ; 79.309,33.208 79.309,33.716 ; 79.309,33.208 79.817,33.208 ; 79.309,33.716 79.309,34.224 ; 79.309,33.716 79.817,33.716 ; 79.309,34.224 79.309,34.732 ; 79.309,34.224 79.543,34.224 ; 79.309,34.732 79.309,35.24 ; 79.309,34.732 79.513,34.732 ; 79.309,35.24 79.309,35.353 ; 79.309,35.24 79.723,35.24 ; 79.309,35.353 79.723,35.767 79.723,35.24 ; 79.309,37.413 79.309,37.78 ; 79.309,37.413 79.746,37.851 79.817,37.921 ; 79.309,37.78 CN1.1@79.309,38.288 ; CN1.1@79.309,38.288 79.817,38.288 ; CN1.1@79.309,38.288 CN1.1@79.309,38.796 ; CN1.1@79.309,38.796 79.817,38.796 ; CN1.1@79.309,38.796 CN1.1@79.309,39.304 ; CN1.1@79.309,39.304 79.817,39.304 ; CN1.1@79.309,39.304 CN1.1@79.309,39.337 ; CN1.1@79.309,39.337 79.817,39.337 ; 79.309,47.319 79.309,47.432 ; 79.309,47.319 79.731,47.319 79.817,47.405 ; 79.309,47.432 79.817,47.432 ; 79.309,47.432 79.309,47.94 ; 79.309,47.94 79.309,48.448 ; 79.309,47.94 79.817,47.94 ; 79.309,48.448 79.309,48.956 ; 79.309,48.448 79.817,48.448 ; 79.309,48.956 79.309,49.464 ; 79.309,48.956 79.817,48.956 ; 79.309,49.464 79.309,49.972 ; 79.309,49.464 79.817,49.464 ; 79.309,49.972 79.309,50.48 ; 79.309,49.972 79.817,49.972 ; 79.309,50.48 79.309,50.988 ; 79.309,50.48 79.817,50.48 ; 79.309,50.988 79.817,50.988 ; 79.309,50.988 79.309,51.496 ; 79.309,51.496 79.817,51.496 ; 79.309,51.496 79.309,52.004 ; 79.309,52.004 79.309,52.512 ; 79.309,52.004 79.817,52.004 ; 79.309,52.512 79.817,52.512 ; 79.309,52.512 79.309,53.02 ; 79.309,53.02 79.309,53.528 ; 79.309,53.02 79.817,53.02 ; 79.309,53.528 79.309,54.036 ; 79.309,53.528 79.817,53.528 ; 79.309,54.036 79.817,54.036 ; 79.309,54.036 79.309,54.544 ; 79.309,54.544 79.309,55.052 ; 79.309,54.544 79.817,54.544 ; 79.309,55.052 79.309,55.56 ; 79.309,55.052 79.817,55.052 ; 79.309,55.56 79.309,56.068 ; 79.309,55.56 79.817,55.56 ; 79.309,56.068 79.817,56.068 ; 79.309,56.068 79.309,56.489 79.309,56.576 ; 79.309,56.576 79.817,56.576 ; 79.309,56.576 79.309,57.084 ; 79.309,57.084 79.817,57.084 ; 79.309,57.084 79.309,57.592 ; 79.309,57.592 79.817,57.592 ; 79.309,57.592 79.309,58.1 ; 79.309,58.1 79.309,58.608 ; 79.309,58.1 79.817,58.1 ; 79.309,58.608 79.309,59.116 ; 79.309,58.608 79.817,58.608 ; 79.309,59.116 79.309,59.624 ; 79.309,59.116 79.817,59.116 ; 79.309,59.624 pad.@79.309,60.132 ; 79.309,59.624 79.817,59.624 ; pad.@79.309,60.132 79.817,60.132 ; pad.@79.309,60.132 79.309,60.64 ; 79.309,60.64 79.817,60.64 ; 79.309,60.64 79.309,61.148 ; 79.309,61.148 79.309,61.656 ; 79.309,61.148 79.817,61.148 ; 79.309,61.656 79.817,61.656 ; 79.309,61.656 79.309,62.164 ; 79.309,62.164 79.817,62.164 ; 79.513,34.732 ccw(c80.475,34.534) 79.541,34.23 ccw(c80.475,34.534) 79.543,34.224 ; 79.543,34.224 ccw(c80.475,34.534) 79.817,33.804 ; 79.817,20.889 79.817,21.016 ; 79.817,20.889 80.325,20.889 ; 79.817,21.016 79.817,21.524 ; 79.817,21.016 80.325,21.016 ; 79.817,21.524 pad.@80.325,21.524 ; 79.817,21.524 79.817,21.889 ; 79.817,21.889 79.899,21.889 79.899,22.032 ; 79.817,26.571 79.817,26.604 ; 79.817,26.571 80.325,26.571 ; 79.817,26.604 79.817,27.112 ; 79.817,26.604 80.325,26.604 ; 79.817,27.112 79.817,27.62 ; 79.817,27.112 80.325,27.112 ; 79.817,27.62 79.817,28.128 ; 79.817,27.62 80.325,27.62 ; 79.817,28.128 79.817,28.636 ; 79.817,28.128 80.325,28.128 ; 79.817,28.636 79.817,29.144 ; 79.817,28.636 80.325,28.636 ; 79.817,29.144 79.817,29.652 ; 79.817,29.144 80.325,29.144 ; 79.817,29.652 80.325,29.652 ; 79.817,29.652 79.817,30.16 ; 79.817,30.16 79.817,30.668 ; 79.817,30.16 80.325,30.16 ; 79.817,30.668 79.817,31.176 ; 79.817,30.668 80.325,30.668 ; 79.817,31.176 79.817,31.684 ; 79.817,31.176 80.325,31.176 ; 79.817,31.684 79.817,32.192 ; 79.817,31.684 80.325,31.684 ; 79.817,32.192 79.817,32.7 ; 79.817,32.192 80.325,32.192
